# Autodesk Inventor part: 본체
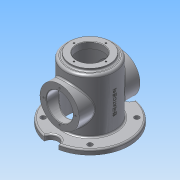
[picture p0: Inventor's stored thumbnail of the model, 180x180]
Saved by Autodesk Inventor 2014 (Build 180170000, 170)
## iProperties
Created: 2018-04
Part Number: 본체
Material: 알루미늄 6061
Document SubType Name: Modeling
Designer: user
Density: 2.71 g/cm^3
Appearance: 알루미늄 - 평지
Mass: 1151.48 g
Surface Area: 1200.97 cm^2
Volume: 424.901 cm^3
Author: user
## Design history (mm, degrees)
sketch "스케치1"
  geometry: C1 r 50 at (0, 0); 1 further point
  constraints: 1 centre point, 1 coincident
  dimensions: "d0" = 100 diameter of C1
extrude "돌출1" new body sketch "스케치1" distance "d1" = 128; taper "d2" = 0 deg
sketch "스케치2"
  geometry: C1 r 50 at (0, 0) reference; C2 r 40 at (0, 0)
  constraints: 1 centre point, 1 coincident
  dimensions: "d3" = 80 diameter of C2
extrude "돌출2" join sketch "스케치2" distance "d4" = 5; taper "d5" = 0 deg
node "작업 평면1"
sketch "스케치3"
  geometry: C1 r 80 at (0, 0); 1 further point
  constraints: 1 centre point, 1 coincident
  dimensions: "d7" = 160 diameter of C1
extrude "돌출3" join sketch "스케치3" distance "d8" = 10; taper "d9" = 0 deg
sketch "스케치4"
  geometry: C1 r 40 at (0, 0) reference; C2 r 27 at (0, 0)
  constraints: 1 centre point, 1 coincident
  dimensions: "d10" = 54 diameter of C2
extrude "돌출4" cut sketch "스케치4" stored distance "d11" = 10; taper "d12" = 0 deg
sketch "스케치5"
  geometry: C1 r 27 at (0, 0) reference; C2 r 50 at (0, 0) reference; C3 r 45 at (0, 0)
  constraints: 1 centre point, 1 coincident
  dimensions: "d13" = 90 diameter of C3
extrude "돌출5" cut sketch "스케치5" distance "d14" = 120; taper "d15" = 0 deg
node "작업 평면2"
sketch "스케치6"
  geometry: L1 (-80, 8)-(80, 8) reference; C1 r 40 at (0, 68); 1 further point
  constraints: 1 centre point, 1 vertical alignment
  dimensions: "d17" = 80 diameter of C1; "d18" = 60 distance from line of C1.centre L1
extrude "돌출6" join sketch "스케치6" distance "d19" = 124; taper "d20" = 0 deg
sketch "스케치7"
  geometry: C1 r 40 at (0, 0) reference; C2 r 27 at (0, 0); 1 further point
  constraints: 1 centre point, 1 coincident
  dimensions: "d21" = 54 diameter of C2
extrude "돌출7" cut sketch "스케치7" stored distance "d22" = 124; taper "d23" = 0 deg
sketch "스케치8"
  geometry: C1 r 15 at (0, -80); C2 r 15 at (0, 80); C3 r 80 at (0, 0) reference; A1 r 80 centre (0, 0) between (0, -80) and (0, 80) reference
  constraints: 2 centre point, 2 point on circle, 2 vertical alignment
  dimensions: "d24" = 30 diameter of C1; "d25" = 30 diameter of C2
extrude "돌출8" cut sketch "스케치8" distance "d26" = 124; taper "d27" = 0 deg
sketch "스케치9" dims "d30" = 135
  geometry: L1 (0, 0)-(-80, 0); L2 (0, 0)-(-56.569, -56.569); L3 (0, 0)-(-56.569, 56.569); L4 (0, 0)-(56.569, -56.569); L5 (0, 0)-(56.569, 56.569); L6 (0, 0)-(-56.569, 56.569); C1 r 45 at (0, 0) reference; C2 r 50 at (0, 0) reference; C3 r 5 at (-47.73, -47.73); C4 r 5 at (47.73, -47.73); C5 r 5 at (47.73, 47.73); C6 r 5 at (-47.73, 47.73); A1 r 80 centre (0, 0) between (-14.934, 78.594) and (-14.934, -78.594) reference; A2 r 15 centre (0, -80) between (14.934, -78.594) and (-14.934, -78.594) reference; A3 r 80 centre (0, 0) between (-14.934, 78.594) and (-14.934, -78.594) reference; A4 r 15 centre (0, 80) between (-14.934, 78.594) and (14.934, 78.594) reference; A5 r 80 centre (0, 0) between (14.934, -78.594) and (14.934, 78.594) reference; 1 further point
  constraints: 12 end point, 5 point on circle, 4 centre point, 4 point on line, 1 coincident, 24 other
  dimensions: "d28" = 45 deg angle of L1 L2; "d29" = 90 deg angle of L3 L2; "d31" = 10 diameter of C3; "d34" = 360 deg dimension on A1.centre L2.end (derived)
extrude "돌출9" cut sketch "스케치9" distance "d36" = 124; taper "d37" = 0 deg
node "작업 평면3"
sketch "스케치10"
  geometry: 2 further points
  constraints: 1 vertical alignment, 1 other
  dimensions: "d39" = 70 distance of point (0, 0) point (0, 70)
feature "엠보싱1" sketch "스케치10" dims "d40" = 0.5, "d41" = 0
sketch "스케치11" dims "d42" = 65
  geometry: C1 r 27 at (0, 0) reference; C2 r 40 at (0, 0) reference; 5 further points
  constraints: 2 horizontal alignment, 1 coincident, 7 other
  dimensions: "d45" = 360 deg dimension on C1.centre point (-32.5, 0) (derived)
hole "구멍1" sketch "스케치11" at (-32.5, 0), (0, -32.5), (32.5, 0), (0, 32.5) diameter "d47" = 3.242; stored, may be unused: countersink angle "d51" = 90 deg, drill point angle "d53" = 118 deg; dims "d48" = 8, "d49" = 4, "d50" = 2, "d52" = 10
sketch "스케치12" dims "d54" = 65
  geometry: C1 r 27 at (0, 0) reference; C2 r 40 at (0, 0) reference; 6 further points
  constraints: 2 vertical alignment, 1 coincident, 7 other
  dimensions: "d57" = 360 deg dimension on C1.centre point (0, 32.5) (derived)
hole "구멍2" sketch "스케치12" at (0, 32.5), (-32.5, 0), (0, -32.5), (32.5, 0) diameter "d59" = 3.242; stored, may be unused: countersink angle "d63" = 90 deg, drill point angle "d65" = 118 deg; dims "d60" = 8, "d61" = 4, "d62" = 2, "d64" = 10
fillet "모깎기1" dims "d66" = 5
fillet "모깎기2" dims "d67" = 3
chamfer "모따기1" distance "d68" = 1; stored, may be unused: second distance "d69" = 2, angle "d70" = 45 deg
fillet "모깎기3" dims "d71" = 3
sketch "스케치13"
  geometry: C1 r 45 at (0, 0) reference; C2 r 50 at (0, 0) reference; C3 r 45 at (0, 0)
  constraints: 1 centre point, 1 coincident
  dimensions: "d72" = 90 diameter of C3
extrude "돌출10" cut sketch "스케치13" distance "d73" = 115; taper "d74" = 0 deg
chamfer "모따기2" distance "d75" = 1; stored, may be unused: second distance "d76" = 2, angle "d77" = 45 deg
fillet "모깎기4" dims "d78" = 3
node "솔리드1"
mirror "대칭1"
node "절단 모서리 투영1"
other parameters: "d6" = 8, "d16" = 62
